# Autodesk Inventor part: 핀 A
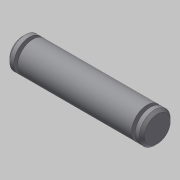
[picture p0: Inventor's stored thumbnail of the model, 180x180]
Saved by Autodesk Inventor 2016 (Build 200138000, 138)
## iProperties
Created: 2020-02
Part Number: 핀 A
Material: 스테인리스강
Document SubType Name: Modeling
Designer: mduedu
Density: 1 g/cm^3
Appearance: 기본값
Author: mduedu
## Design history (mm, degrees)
sketch "스케치1"
  geometry: L1 (0, 0)-(26, 0); L2 (26, 0)-(26, 3); L3 (26, 3)-(0, 3); L4 (0, 3)-(0, 0)
  constraints: 8 end point, 2 parallel, 1 horizontal, 1 perpendicular
  dimensions: "d0" = 26 distance of L2.end L3.end; "d2" = 6 diameter of L3 L1
revolve "회전1" sketch "스케치1" stored, may be unused: angle "d3" = 90 deg
sketch "스케치2"
  geometry: L1 (0, -3)-(0, 3) reference; L2 (0, 3)-(26, 3) reference; L3 (26, 3)-(26, -3) reference; L4 (26, -3)-(0, -3) reference; L5 (0, 0)-(26, 0); L6 (1.3, 3)-(2, 3); L7 (2, 3)-(2, 2); L8 (2, 2)-(1.3, 2); L9 (1.3, 2)-(1.3, 3)
  constraints: 10 end point, 2 parallel, 1 horizontal, 1 midpoint, 1 perpendicular, 1 point on line
  dimensions: "d4" = 4 diameter of L8 L5; "d6" = 1.3 distance between parallel lines of L9 L1; "d7" = 0.7 distance between parallel lines of L7 L9
revolve "회전2" sketch "스케치2" stored, may be unused: angle "d8" = 90 deg
node "작업 평면1"
chamfer "모따기1" distance "d9" = 0.5; stored, may be unused: second distance "d10" = 2, angle "d11" = 45 deg
node "솔리드1"
mirror "대칭1"
node "절단 모서리 투영1"
